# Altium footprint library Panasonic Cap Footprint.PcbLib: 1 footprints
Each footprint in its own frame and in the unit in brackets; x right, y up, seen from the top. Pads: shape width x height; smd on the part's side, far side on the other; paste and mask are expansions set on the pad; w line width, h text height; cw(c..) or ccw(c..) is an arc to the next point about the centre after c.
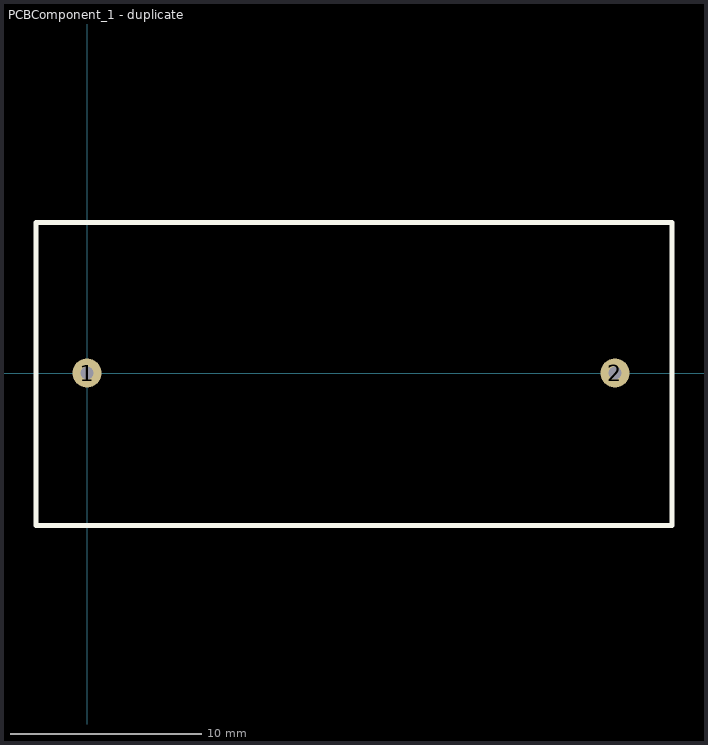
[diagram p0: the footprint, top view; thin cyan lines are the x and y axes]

## PCBComponent_1 - duplicate [mil]
pads (2):
  round 60 hole 27.56: 1(0,0) 2(1082.68,0)
Top Overlay:
  lines w10: -105,-313 -105,309 1200,309 1200,-313 203,-313 -105,-313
